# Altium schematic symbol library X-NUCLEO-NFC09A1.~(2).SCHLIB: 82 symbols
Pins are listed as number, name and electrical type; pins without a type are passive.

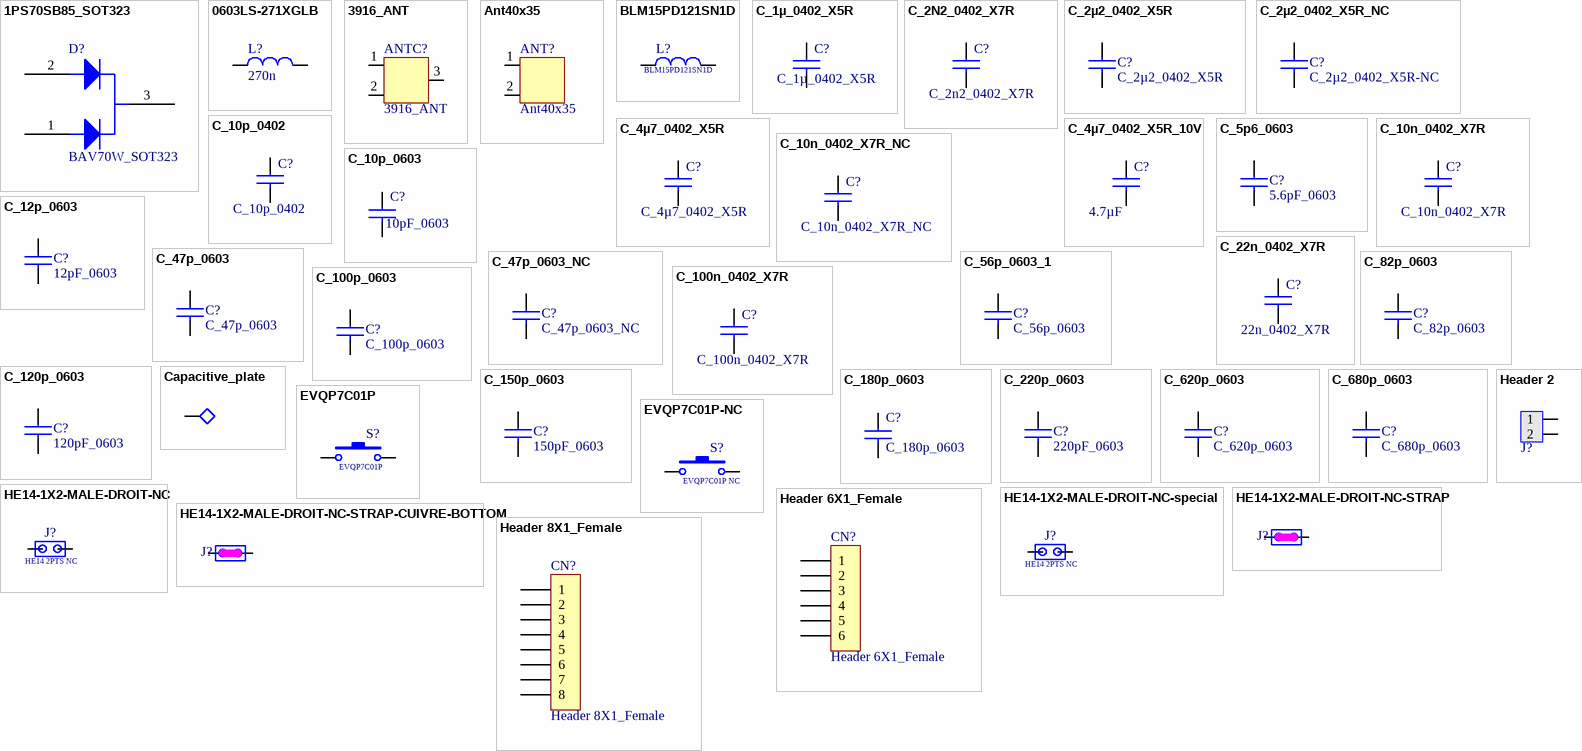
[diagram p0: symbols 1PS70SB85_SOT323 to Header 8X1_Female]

## 1PS70SB85_SOT323
designator D?, comment BAV70W_SOT323
footprint SOT323
pins: 1 A1, 2 A2, 3 K

## 0603LS-271XGLB
designator L?, comment 270n
0603LS-271XGLB; Manufacturer: COILCRAFT
footprint L0603
pins: 1, 2

## 3916_ANT
designator ANTC?  (net tie, no BOM)
ST25R3916 DB Ant
footprint ST25R_3916DB_18x18mm 0.325mm (18mm x 18mm)
footprint ST25R_3916DB_40x40mm 4 Turn 1mm (40mm x 40mm)
footprint ST25R_3916DB_66x66mm (66mm x 66mm)
footprint ST25R_3916DB_combo v2.0 (66mm x 66mm)
pins: 1, 2, 3

## Ant40x35
designator ANT?  (net tie, no BOM)
footprint ANT40x35 (40mm times 35mm)
pins: 1, 2, 3 hidden

## BLM15PD121SN1D
designator L?
FERRITE BEAD; Manufacturer: MURATA
footprint L0402
pins: 1, 2

## C_1µ_0402_X5R
designator C?
1u_X5R; Manufacturer: MURATA; Manufacturer Part Number: GRM155R61C105KA12D; 2nd Source: 0402, 1 µF, 16 V, ± 10%, X5R,
footprint C0402
pins: 1, 2

## C_2N2_0402_X7R
designator C?, comment C_2n2_0402_X7R
2N2_x7R; Manufacturer: AVX; Manufacturer Part Number: 04023C222KAT2A; 2nd Source: 0402, 2.2 nF, 25 V, ± 10%, X7R
footprint C0402
pins: 1, 2

## C_2µ2_0402_X5R
designator C?
2u2_X5R; Manufacturer: MURATA; Manufacturer Part Number: GRM155R60J225ME15D; 2nd Source: 0402, 2.2 µF, 6.3 V, ± 20%, X5R
footprint C0402
pins: 1, 2

## C_2µ2_0402_X5R_NC
designator C?, comment C_2µ2_0402_X5R-NC
2u2_X5R NC; Manufacturer: MURATA; Manufacturer Part Number: GRM155R60J225ME15D NOT FITTED; 2nd Source: 0402, 2.2 µF, 6.3 V, ± 20%, X5R
footprint C0402
pins: 1, 2

## C_4µ7_0402_X5R
designator C?
4u7_X5R; Manufacturer: TDK; Manufacturer Part Number: C1005X5R0J475K050BC; 2nd Source: 0402, 4.7 µF, 6.3 V, ± 10%, X5R
footprint C0402
pins: 1, 2

## C_4µ7_0402_X5R_10V
designator C?, comment 4.7µF
4u7_X5R_10V_0402; Manufacturer: MURATA; Manufacturer Part Number: GRM155R61A475MEAA
footprint C0402
pins: 1, 2

## C_5p6_0603
designator C?, comment 5.6pF_0603
5p6_COG 0603; Manufacturer: MURATA; Manufacturer Part Number: GRM1885C1H5R6CA01D
footprint C0603
pins: 1, 2

## C_10n_0402_X7R
designator C?
10n_x7R; Manufacturer: AVX; Manufacturer Part Number: 04023C103KAT2A; 2nd Source: 0402, 0.01 µF, 25 V, ± 10%, X7R
footprint C0402
pins: 1, 2

## C_10n_0402_X7R_NC
designator C?
10n_x7R NC; Manufacturer: AVX; Manufacturer Part Number: 04023C103KAT2A NOT FITTED; 2nd Source: 0402, 0.01 µF, 25 V, ± 10%, X7R
footprint C0402
pins: 1, 2

## C_10p_0402
designator C?
10p_C0G; Manufacturer: MURATA; Manufacturer Part Number: GRM1555C1H100GA01D; 2nd Source: 0402, 0.01 µF, 25 V, ± 10%, X7R
footprint C0402
pins: 1, 2

## C_10p_0603
designator C?, comment 10pF_0603
10p_COG; Manufacturer: MULTICOMP; Manufacturer Part Number: MC0603N100F500CT
footprint C0603
pins: 1, 2

## C_12p_0603
designator C?, comment 12pF_0603
12pF_COG 0603; Manufacturer: MULTI-SOURCES; Manufacturer Part Number: 0603 12pF 2% C0G 25V MIN
footprint C0603
pins: 1, 2

## C_22n_0402_X7R
designator C?, comment 22n_0402_X7R
22nF_x7R_0402; Manufacturer: AVX; Manufacturer Part Number: 0402YC223KAT2A; 2nd Source: 0402, 22nF, 16 V, ± 10%, X7R
footprint C0402
pins: 1, 2

## C_47p_0603
designator C?
47p_COG; Manufacturer: MURATA; Manufacturer Part Number: GRM1885C1H470FA01D; 2nd Source: 47pF ±2% 50V  C0G, NP0 0603
footprint C0603
pins: 1, 2

## C_47p_0603_NC
designator C?
47p_COG_NC; Manufacturer: MURATA; Manufacturer Part Number: GRM1885C1H470FA01D; 2nd Source: 47pF ±2% 50V  C0G, NP0 0603 NOT FITTED
footprint C0603
pins: 1, 2

## C_56p_0603_1
designator C?, comment C_56p_0603
56p_COG; Manufacturer: MURATA; Manufacturer Part Number: GRM1885C1H560FA01D; 2nd Source: 56pF ±2% 50V  C0G, NP0 0603
footprint C0603
pins: 1, 2

## C_82p_0603
designator C?
82p_COG; Manufacturer: MURATA; Manufacturer Part Number: GRM1885C1H820FA01D; 2nd Source: 82pF ±2% 50V  C0G, NP0 0603
footprint C0603
pins: 1, 2

## C_100n_0402_X7R
designator C?
100n_x7R 0402; Manufacturer: MULTICOMP; Manufacturer Part Number: MC0402X104K100CT; 2nd Source: 0402, 0.1 µF, 10 V, ± 10%, X7R
footprint C0402
pins: 1, 2

## C_100p_0603
designator C?
100p_COG; Manufacturer: MURATA; Manufacturer Part Number: GRM1885C1H101FA01D; 2nd Source: 100pF ±2% 50V  C0G, NP0 0603
footprint C0603
pins: 1, 2

## C_120p_0603
designator C?, comment 120pF_0603
120pF_COG; Manufacturer: MULTI-SOURCES; Manufacturer Part Number: 120pF ±2% 50V  C0G, NP0 0603; 2nd Source: 100pF ±2% 50V  C0G, NP0 0603
footprint C0603
pins: 1, 2

## C_150p_0603
designator C?, comment 150pF_0603
150p_COG 0603; Manufacturer: MURATA; Manufacturer Part Number: GRM1885C1H151GA01D
footprint C0603
pins: 1, 2

## C_180p_0603
designator C?
180p_COG; Manufacturer: MURATA; Manufacturer Part Number: GRM1885C1H181GA01D; 2nd Source: 180pF ±2% 50V  C0G, NP0 0603
footprint C0603
pins: 1, 2

## C_220p_0603
designator C?, comment 220pF_0603
220p_COG 0603; Manufacturer: MURATA; Manufacturer Part Number: GRM1885C1H221FA01D
footprint C0603
pins: 1, 2

## C_620p_0603
designator C?
620p_COG 0603; Manufacturer: MURATA; Manufacturer Part Number: GCM1885C2A621FA16J
footprint C0603
pins: 1, 2

## C_680p_0603
designator C?
680p_COG; Manufacturer: MURATA; Manufacturer Part Number: GRM1885C1H681GA01D; 2nd Source: 680pF ±2% 50V  C0G, NP0 0603
footprint C0603
pins: 1, 2

## Capacitive_plate
designator CP?, comment CS1  (value not drawn)  (no BOM)
Capacitive Sensing
footprint Capacitive_plate
pins: 1

## EVQP7C01P
designator S?
SIDE SWITCH; Manufacturer: PANASONIC
footprint PANASONIC-SWITCH-EVQP7C/EVQP7L
pins: 1, 2

## EVQP7C01P-NC
designator S?, comment EVQP7C01P NC
SIDE SWITCH NOT FITTED; Manufacturer: PANASONIC; Manufacturer Part Number: EVQP7C01P NOT FITTED
footprint PANASONIC-SWITCH-EVQP7C/EVQP7L
pins: 1, 2

## HE14-1X2-MALE-DROIT-NC
designator J?, comment HE14 2PTS NC
CONN HE14 2PTS MALE VERTICAL NOT FITTED; Manufacturer: MULTI-SOURCES; 2nd Source: doublesourcing allowed
footprint HE14-1x2-DROIT-SANS-3D
pins: 1, 2

## HE14-1X2-MALE-DROIT-NC-special
designator J?, comment HE14 2PTS NC
CONN HE14 2PTS MALE VERTICAL NOT FITTED; Manufacturer: MULTI-SOURCES; 2nd Source: doublesourcing allowed
footprint HE14-1x2-DROIT-sans-3D-largeur-1.8
pins: 1, 2

## HE14-1X2-MALE-DROIT-NC-STRAP
designator J?, comment HE14 2PTS NC  (value not drawn)
CONN HE14 2PTS MALE VERTICAL NOT FITTED; 2nd Source: doublesourcing allowed
footprint HE14-1x2-DROIT-AVEC-STRAP-EN-ASM
pins: 1, 2

## HE14-1X2-MALE-DROIT-NC-STRAP-CUIVRE-BOTTOM
designator J?, comment HE14 2PTS NC  (value not drawn)  (net tie)
CONN HE14 2PTS MALE VERTICAL NOT FITTED; 2nd Source: doublesourcing allowed
footprint HE14-1x2-DROIT-AVEC-STRAP-CUIVRE-BOTTOM
pins: 1, 2

## Header 2
designator J?, comment Male Single Row Horizontal  (value not drawn)
Male Single Row Horizontal 2 pin; 2nd Source: doublesourcing allowed
footprint HDR1X2_slim (Connector; Header; 2 Position)
pins: 1, 2

## Header 6X1_Female
designator CN?
Header, 6-Pin, Single row,female; Manufacturer: Samtec; Manufacturer Part Number: SSQ-106-03-L-S; Comments: RECEPTACLE, 2.54MM, SINGLE ROW, 6 WAY; 2nd source: doublesourcing allowed
footprint SAMTEC-SSQ-1x6-DROIT-STYLE-03
pins: 1, 2, 3, 4, 5, 6

## Header 8X1_Female
designator CN?
Header, 8-Pin, Single row,female; Manufacturer: Samtec; Manufacturer Part Number: SSQ-108-03-L-S; Comments: RECEPTACLE, 2.54MM, SINGLE ROW, 8WAY; 2nd source: doublesourcing allowed
footprint SAMTEC-SSQ-1x8-DROIT-STYLE-03
pins: 1, 2, 3, 4, 5, 6, 7, 8

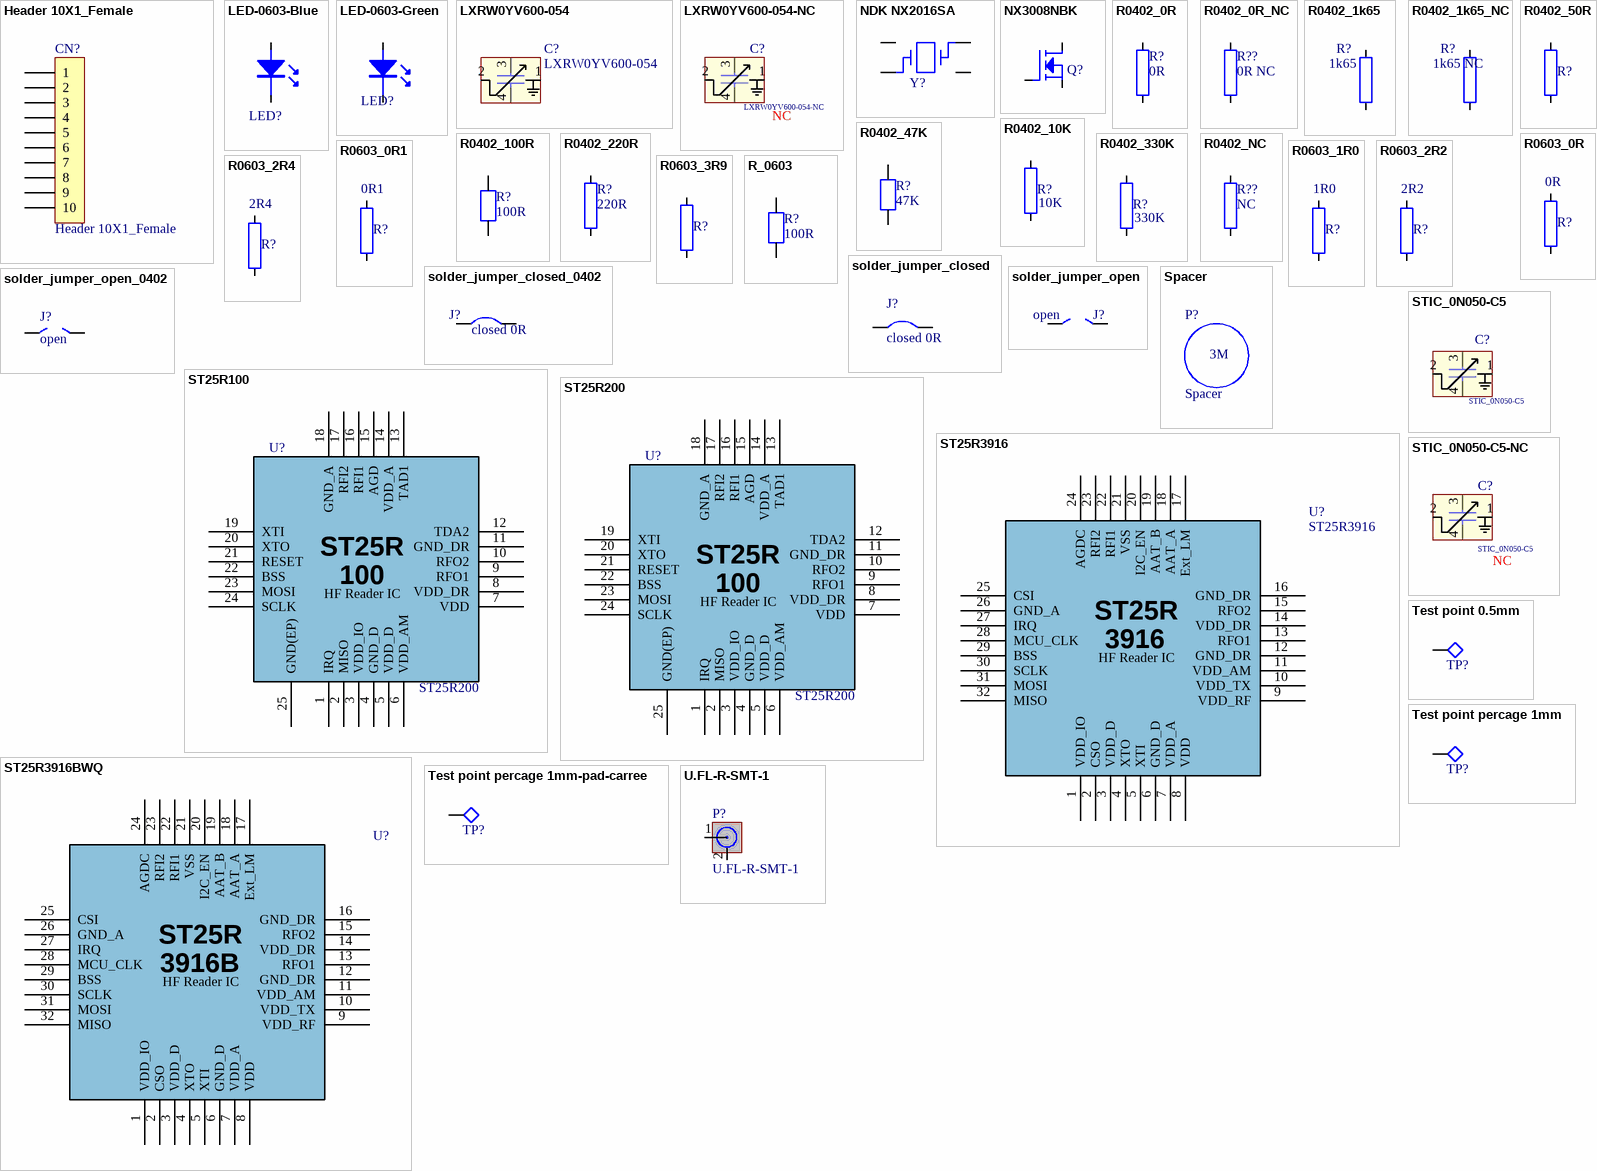
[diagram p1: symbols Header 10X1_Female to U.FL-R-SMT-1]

## Header 10X1_Female
designator CN?
Header, 10-Pin, Single row,female; Manufacturer: Samtec; Manufacturer Part Number: SSQ-110-03-L-S; Comments: RECEPTACLE, 2.54MM, SINGLE ROW, 10WAY; 2nd source: doublesourcing allowed
footprint SAMTEC-SSQ-1x10-DROIT-STYLE-03
pins: 1, 2, 3, 4, 5, 6, 7, 8, 9, 10

## LED-0603-Blue
designator LED?, comment Blue  (value not drawn)
Manufacturer: Lite-On; Manufacturer Part Number: LTST-C190TBKT
footprint D0603
pins: 1, 2

## LED-0603-Green
designator LED?, comment Green  (value not drawn)
Manufacturer: Lite-On; Manufacturer Part Number: LTST-C190KGKT
footprint D0603
pins: 1, 2

## LXRW0YV600-054
designator C?
VARIABLE CAPACITOR LXRW0YV600-054; Manufacturer: muRata
footprint MURATA-VARIABLE-CAPA-LXRW-0Y
pins: 1, 2, 3, 4

## LXRW0YV600-054-NC
designator C?  POPULATED: NC
VARIABLE CAPACITOR LXRW0YV600-054 NOT FITTED; Manufacturer: muRata
footprint MURATA-VARIABLE-CAPA-LXRW-0Y
pins: 1, 2, 3, 4

## NDK NX2016SA
designator Y?, comment NDK 27,12MHz Crystal  (value not drawn)
NDK NX2016SA 27.12MHz; Manufacturer Part Number: NX2016SA STD-CZS-5 27.12MHz; 2nd Source: Murata XRCGB27M120F3M00R0
footprint XRCGB_F_MN
pins: 1, 2, 3, 4

## NX3008NBK
designator Q?  (value not drawn)
nCh MOS Fet - NX3008NBK
footprint SOT23
pins: 1 G, 2 S, 3 D

## R0402_0R
designator R?, comment 0R
0R, 0402; Manufacturer: MULTI-SOURCES; Manufacturer Part Number: RESISTOR 0402 0R 62mW; 2nd Source: 0 ohm, 50 V, 0402, >62.5 mW
footprint R0402
pins: 1, 2

## R0402_0R_NC
designator R??, comment 0R NC
0R, 0402 NOT FITTED; Manufacturer: MULTICOMP; Manufacturer Part Number: MC00625W040210R NOT FITTED; 2nd Source: 0 ohm, 50 V, 0402, >62.5 mW NOT FITTED
footprint R0402
pins: 1, 2

## R0402_1k65
designator R?, comment 1k65
1k65, 0402; Manufacturer: MULTICOMP; Manufacturer Part Number: MC00625W040211K65; 2nd Source: 1.65 kohm, 50 V, 0402, >62.5 mW, ± 1%
footprint R0402
pins: 1, 2

## R0402_1k65_NC
designator R?, comment 1k65 NC
1k65, 0402 NOT FITTED; Manufacturer: MULTICOMP; Manufacturer Part Number: MC00625W040211K65 NOT FITTED; 2nd Source: 1.65 kohm, 50 V, 0402, >62.5 mW, ± 1% NOT FITTED
footprint R0402
pins: 1, 2

## R0402_10K
designator R?, comment 10K
10K, 0402; Manufacturer: MULTI-SOURCES; Manufacturer Part Number: 0402 10K 1%
footprint R0402
pins: 1, 2

## R0402_47K
designator R?, comment 47K
47K 0402
footprint R0402
pins: 1, 2

## R0402_50R
designator R?, comment 50R  (value not drawn)
50R, 0402; Manufacturer: MULTICOMP; Manufacturer Part Number: MCMR04X49R9FTL; 2nd Source: 49.9 ohm, 50 V, 0402, >62.5 mW, ± 1%
footprint R0402
pins: 1, 2

## R0402_100R
designator R?, comment 100R
100R 0402
footprint R0402
pins: 1, 2

## R0402_220R
designator R?, comment 220R
220R, 0402; Manufacturer: Yageo; Manufacturer Part Number: RC0402JR-07220RL; 2nd Source: 220 Ohm ±5% 0.063W, 1/16W Chip Resistor 0402
footprint R0402
pins: 1, 2

## R0402_330K
designator R?, comment 330K
330K, 0402; Manufacturer: MULTI-SOURCES; Manufacturer Part Number: 0402 330K 1%
footprint R0402
pins: 1, 2

## R0402_NC
designator R??, comment NC
0402 NOT FITTED; 2nd Source: 0 ohm, 50 V, 0402, >62.5 mW
footprint R0402
pins: 1, 2

## R0603_0R
designator R?, comment 0R
0R, 0603; Manufacturer: MULTI-SOURCES; Manufacturer Part Number: RESISTOR 0603 0R 62mW
footprint R0603
pins: 1, 2

## R0603_0R1
designator R?, comment 0R1
0R1, 0603; Manufacturer: OHMITE; Manufacturer Part Number: KDV06DR100ET
footprint R0603
pins: 1, 2

## R0603_1R0
designator R?, comment 1R0
1R0, 0603; Manufacturer: VISHAY; Manufacturer Part Number: CRCW06031R00FKEAHP
footprint R0603
pins: 1, 2

## R0603_2R2
designator R?, comment 2R2
2R2, 0603; Manufacturer: MULTI-SOURCES; Manufacturer Part Number: RESISTOR 0603 2.2 Ohms 1%
footprint R0603
pins: 1, 2

## R0603_2R4
designator R?, comment 2R4
2R4, 0603; Manufacturer: Panasonic; 2nd Source: 2.4 Ohm ±5% 0.1W, 1/10W Chip Resistor 0603
footprint R0603
pins: 1, 2

## R0603_3R9
designator R?, comment 3R9  (value not drawn)
1R0, 0603; Manufacturer: Panasonic; 2nd Source: 1 Ohm ±5% 0.1W, 1/10W Chip Resistor 0603
footprint R0603
pins: 1, 2

## R_0603
designator R?, comment 100R
2nd Source: 100R 0402
footprint R0402
footprint R0603-ss
pins: 1, 2

## solder_jumper_closed
designator J?, comment closed 0R  (net tie)
0R; Manufacturer: Multicomp; Manufacturer Part Number: MC00625W040210R
footprint JP2_SMD_closed
pins: 1, 2

## solder_jumper_closed_0402
designator J?, comment closed 0R  (net tie)
0R 0402; Manufacturer: MULTI-SOURCES; Manufacturer Part Number: RESISTOR 0402 0R 62mW
footprint JP2_SMD_closed_0402
pins: 1, 2

## solder_jumper_open
designator J?, comment open  (net tie, no BOM)
footprint JP2_SMD_open
pins: 1, 2

## solder_jumper_open_0402
designator J?, comment open  (net tie, no BOM)
footprint JP2_SMD_open_0402
pins: 1, 2

## Spacer
designator P?
Samtec; Manufacturer: 3M; Manufacturer Part Number: SJ5303TRANS; 2nd Source: doublesourcing allowed
footprint spacer (spacer d5mmx4mm)

## ST25R100
designator U?, comment ST25R200
HF READER ST25R100 QFN24; Manufacturer: ST MICRO; PickPlace: Yes
footprint ST25R200 QFN (QFN, 24-Leads, Body 4.00x4.00mm, Pitch 0.50mm, Thermal Pad 2.65x2.65mm, IPC Medium Density)
pins: 1 IRQ, 2 MISO, 3 VDD_IO, 4 GND_D, 5 VDD_D, 6 VDD_AM, 7 VDD, 8 VDD_DR, 9 RFO1, 10 RFO2, 11 GND_DR, 12 TDA2, 13 TAD1, 14 VDD_A, 15 AGD, 16 RFI1, 17 RFI2, 18 GND_A, 19 XTI, 20 XTO, 21 RESET, 22 BSS, 23 MOSI, 24 SCLK, 25 GND(EP)

## ST25R200
designator U?
HF READER ST25R200 QFN24; Manufacturer: ST MICRO; PickPlace: Yes
footprint ST25R200 QFN (QFN, 24-Leads, Body 4.00x4.00mm, Pitch 0.50mm, Thermal Pad 2.65x2.65mm, IPC Medium Density)
pins: 1 IRQ, 2 MISO, 3 VDD_IO, 4 GND_D, 5 VDD_D, 6 VDD_AM, 7 VDD, 8 VDD_DR, 9 RFO1, 10 RFO2, 11 GND_DR, 12 TDA2, 13 TAD1, 14 VDD_A, 15 AGD, 16 RFI1, 17 RFI2, 18 GND_A, 19 XTI, 20 XTO, 21 RESET, 22 BSS, 23 MOSI, 24 SCLK, 25 GND(EP)

## ST25R3916
designator U?
NFC Initiator / HF Reader IC; Manufacturer: STMicroelectronics; Manufacturer Part Number: ST25R3916-AQFMCT-ND
footprint ST25R3916-QFN32_5X5_0.5
pins: 1 VDD_IO, 2 CSO, 3 VDD_D, 4 XTO, 5 XTI, 6 GND_D, 7 VDD_A, 8 VDD, 9 VDD_RF, 10 VDD_TX, 11 VDD_AM, 12 GND_DR, 13 RFO1, 14 VDD_DR, 15 RFO2, 16 GND_DR, 17 Ext_LM, 18 AAT_A, 19 AAT_B, 20 I2C_EN, 21 VSS, 22 RFI1, 23 RFI2, 24 AGDC, 25 CSI, 26 GND_A, 27 IRQ, 28 MCU_CLK, 29 BSS, 30 SCLK, 31 MOSI, 32 MISO, 33 VSS (power)

## ST25R3916BWQ
designator U?, comment ST25R3916B  (value not drawn)
NFC Initiator / HF Reader IC; Manufacturer: STMicroelectronics; Manufacturer Part Number: ST25R3916-BQW
footprint ST25R3916-QFN32_5X5_0.5
pins: 1 VDD_IO, 2 CSO, 3 VDD_D, 4 XTO, 5 XTI, 6 GND_D, 7 VDD_A, 8 VDD, 9 VDD_RF, 10 VDD_TX, 11 VDD_AM, 12 GND_DR, 13 RFO1, 14 VDD_DR, 15 RFO2, 16 GND_DR, 17 Ext_LM, 18 AAT_A, 19 AAT_B, 20 I2C_EN, 21 VSS, 22 RFI1, 23 RFI2, 24 AGDC, 25 CSI, 26 GND_A, 27 IRQ, 28 MCU_CLK, 29 BSS, 30 SCLK, 31 MOSI, 32 MISO, 33 VSS (power)

## STIC_0N050-C5
designator C?
VARIABLE CAPACITOR STIC_0N050-C5; Manufacturer: ST MICRO
footprint STMICRO-CAPA-VARIABLE-STIC_0N050-C5
pins: 1, 2, 3, 4

## STIC_0N050-C5-NC
designator C?, comment STIC_0N050-C5  POPULATED: NC
VARIABLE CAPACITOR STIC_0N050-C5 NOT FITTED; Manufacturer: ST MICRO
footprint STMICRO-CAPA-VARIABLE-STIC_0N050-C5
pins: 1, 2, 3, 4

## Test point 0.5mm
designator TP?  (value not drawn)
Part Number: Test point 0.5mm
footprint TP_0.5 (Test Point 0.5mm)
pins: 1 0

## Test point percage 1mm
designator TP?  (no BOM)
Part Number: Test point 0.5mm
footprint 1*1P_MALE round
pins: 1 0

## Test point percage 1mm-pad-carree
designator TP?  (no BOM)
Part Number: Test point 0.5mm
footprint 1*1P_MALE
pins: 1 0

## U.FL-R-SMT-1
designator P?
Manufacturer: HIROSE(HRS); Manufacturer Part Number: U.FL-R-SMT-1(10); 2nd Source: yes
footprint U FL Socket - HRS - Surface Mount
pins: 1, 2, 3

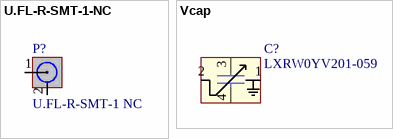
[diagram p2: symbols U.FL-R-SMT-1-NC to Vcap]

## U.FL-R-SMT-1-NC
designator P?, comment U.FL-R-SMT-1 NC
U.FL-R-SMT-1 NOT FITTED; Manufacturer: HIROSE(HRS); Manufacturer Part Number: U.FL-R-SMT-1(10) NOT FITTED; 2nd Source: yes
footprint U FL Socket - HRS - Surface Mount
pins: 1, 2, 3

## Vcap
designator C?, comment LXRW0YV201-059
Manufacturer: muRata
footprint Vcap_csp_combo
pins: 1, 2, 3, 4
